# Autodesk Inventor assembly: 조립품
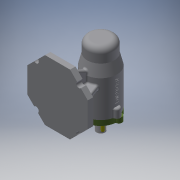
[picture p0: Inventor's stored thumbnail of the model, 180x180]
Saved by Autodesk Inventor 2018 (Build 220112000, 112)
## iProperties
Created: 2019-12
Part Number: 조립품
Document SubType Name: Assembly
Designer: Administrator
Author: Administrator
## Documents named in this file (11)
- C:\Users\Administrator\Desktop\491204V1065\조립품.iam
- C:\Users\Administrator\Desktop\491204V1065\본체.ipt
- C:\Users\Administrator\Desktop\491204V1065\축.ipt
- C:\Users\Administrator\Desktop\491204V1065\베어링 6004.ipt
- C:\Users\Administrator\Desktop\491204V1065\키 5 x 5 x 16.ipt
- C:\Users\Administrator\Desktop\491204V1065\V벨트풀리.ipt
- C:\Users\Administrator\Desktop\491204V1065\어댑터슬리브.ipt
- C:\Users\Administrator\Desktop\491204V1065\볼트 M4.ipt
- C:\Users\Administrator\Desktop\491204V1065\베어링 51202.ipt
- C:\Users\Administrator\Desktop\491204V1065\커버.ipt
- C:\Users\Administrator\Desktop\491204V1065\오일 실.ipt
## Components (1 placed, 1 different names)
1. V벨트풀리:1
